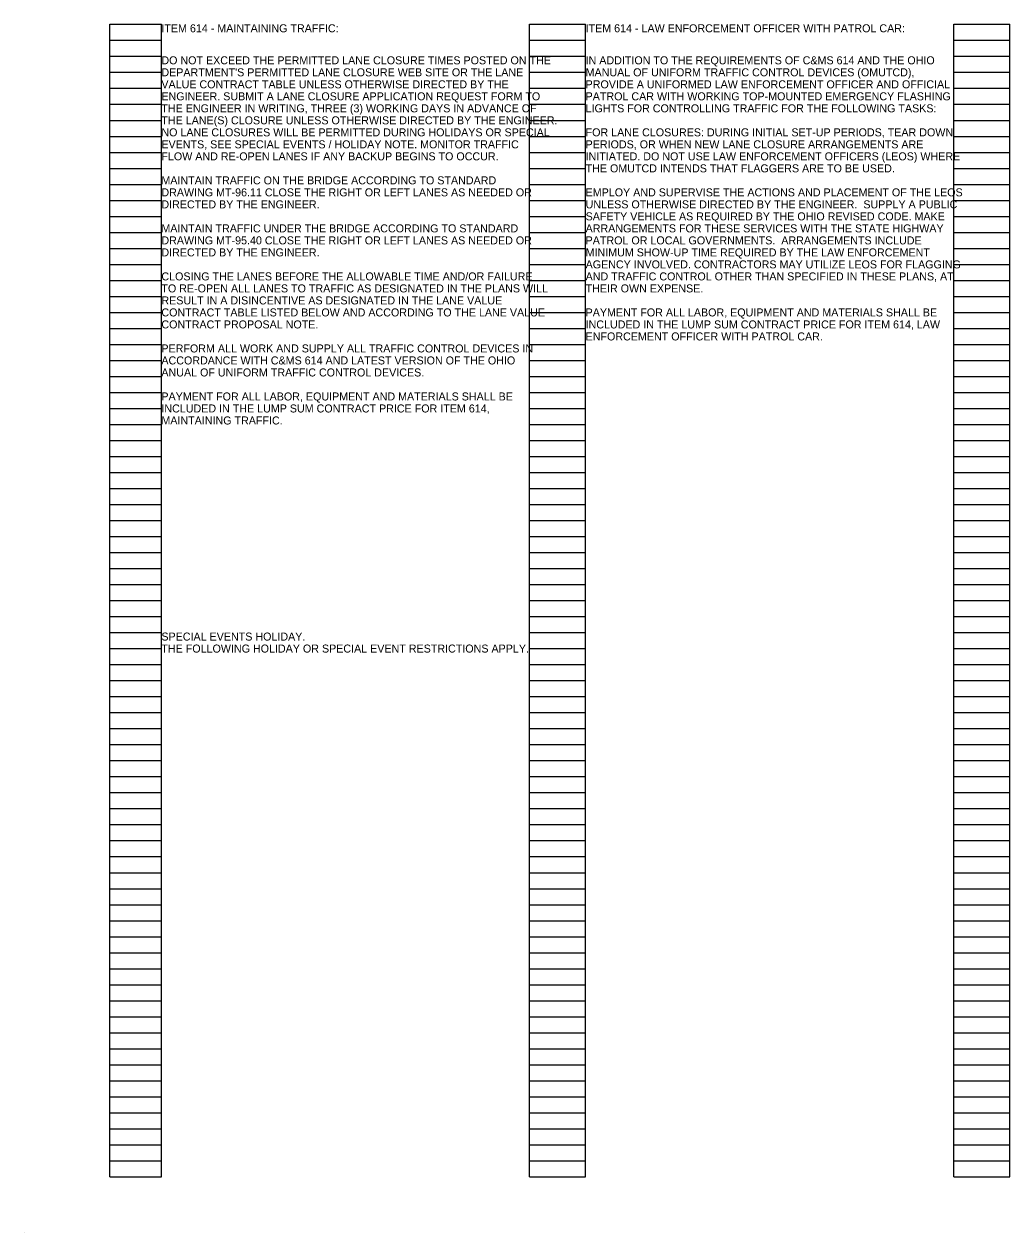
# Model space of a CAD drawing. Extents: x -36 to 68, y -39 to 86.
# Drawn here: x -36 to -18.76, y 0 to 21.14 of the extents above; entities that cross this region are included whole.
import ezdxf

# ---------------------------------------------------------------- set-up
doc = ezdxf.new("R2010")
doc.units = 0
doc.layers.add('SH_Data', color=7, linetype='Continuous')
doc.layers.add('ST_Text', color=7, linetype='Continuous')

msp = doc.modelspace()

# ---------------------------------------------------------------- linework, layer by layer
at = {"layer": 'SH_Data'}
for p, q in [((-34.5, 0.98), (-34.5, 21.14)), ((-34.5, 21.14), (-33.6, 21.14)), ((-33.6, 0.98), (-33.6, 21.14)), ((-27.16, 0.98), (-27.16, 21.14)), ((-27.16, 21.14), (-26.18, 21.14)), ((-26.18, 0.98), (-26.18, 21.14)), ((-19.74, 0.98), (-19.74, 21.14)), ((-19.74, 21.14), (-18.76, 21.14)), ((-18.76, 0.98), (-18.76, 21.14)), ((-34.5, 20.86), (-33.6, 20.86)), ((-27.16, 20.86), (-26.18, 20.86)), ((-19.74, 20.86), (-18.76, 20.86)), ((-34.5, 20.58), (-33.6, 20.58)), ((-27.16, 20.58), (-26.18, 20.58)), ((-19.74, 20.58), (-18.76, 20.58)), ((-34.5, 20.3), (-33.6, 20.3)), ((-27.16, 20.3), (-26.18, 20.3)), ((-19.74, 20.3), (-18.76, 20.3)), ((-34.5, 20.02), (-33.6, 20.02)), ((-27.16, 20.02), (-26.18, 20.02)), ((-19.74, 20.02), (-18.76, 20.02)), ((-34.5, 19.74), (-33.6, 19.74)), ((-27.16, 19.74), (-26.18, 19.74)), ((-19.74, 19.74), (-18.76, 19.74)), ((-34.5, 19.46), (-33.6, 19.46)), ((-27.16, 19.46), (-26.18, 19.46)), ((-19.74, 19.46), (-18.76, 19.46)), ((-34.5, 19.18), (-33.6, 19.18)), ((-27.16, 19.18), (-26.18, 19.18)), ((-19.74, 19.18), (-18.76, 19.18)), ((-34.5, 18.9), (-33.6, 18.9)), ((-27.16, 18.9), (-26.18, 18.9)), ((-19.74, 18.9), (-18.76, 18.9)), ((-34.5, 18.62), (-33.6, 18.62)), ((-27.16, 18.62), (-26.18, 18.62)), ((-19.74, 18.62), (-18.76, 18.62)), ((-34.5, 18.34), (-33.6, 18.34)), ((-27.16, 18.34), (-26.18, 18.34)), ((-19.74, 18.34), (-18.76, 18.34)), ((-34.5, 18.06), (-33.6, 18.06)), ((-27.16, 18.06), (-26.18, 18.06)), ((-19.74, 18.06), (-18.76, 18.06)), ((-34.5, 17.78), (-33.6, 17.78)), ((-27.16, 17.78), (-26.18, 17.78)), ((-19.74, 17.78), (-18.76, 17.78)), ((-34.5, 17.5), (-33.6, 17.5)), ((-27.16, 17.5), (-26.18, 17.5)), ((-19.74, 17.5), (-18.76, 17.5)), ((-34.5, 17.22), (-33.6, 17.22)), ((-27.16, 17.22), (-26.18, 17.22)), ((-19.74, 17.22), (-18.76, 17.22)), ((-34.5, 16.94), (-33.6, 16.94)), ((-27.16, 16.94), (-26.18, 16.94)), ((-19.74, 16.94), (-18.76, 16.94)), ((-34.5, 16.66), (-33.6, 16.66)), ((-27.16, 16.66), (-26.18, 16.66)), ((-19.74, 16.66), (-18.76, 16.66)), ((-34.5, 16.38), (-33.6, 16.38)), ((-27.16, 16.38), (-26.18, 16.38)), ((-19.74, 16.38), (-18.76, 16.38)), ((-34.5, 16.1), (-33.6, 16.1)), ((-27.16, 16.1), (-26.18, 16.1)), ((-19.74, 16.1), (-18.76, 16.1)), ((-34.5, 15.82), (-33.6, 15.82)), ((-27.16, 15.82), (-26.18, 15.82)), ((-19.74, 15.82), (-18.76, 15.82)), ((-34.5, 15.54), (-33.6, 15.54)), ((-27.16, 15.54), (-26.18, 15.54)), ((-19.74, 15.54), (-18.76, 15.54)), ((-34.5, 15.26), (-33.6, 15.26)), ((-27.16, 15.26), (-26.18, 15.26)), ((-19.74, 15.26), (-18.76, 15.26)), ((-34.5, 14.98), (-33.6, 14.98)), ((-27.16, 14.98), (-26.18, 14.98)), ((-19.74, 14.98), (-18.76, 14.98)), ((-34.5, 14.7), (-33.6, 14.7)), ((-27.16, 14.7), (-26.18, 14.7)), ((-19.74, 14.7), (-18.76, 14.7)), ((-34.5, 14.42), (-33.6, 14.42)), ((-27.16, 14.42), (-26.18, 14.42)), ((-19.74, 14.42), (-18.76, 14.42)), ((-34.5, 14.14), (-33.6, 14.14)), ((-27.16, 14.14), (-26.18, 14.14)), ((-19.74, 14.14), (-18.76, 14.14)), ((-34.5, 13.86), (-33.6, 13.86)), ((-27.16, 13.86), (-26.18, 13.86)), ((-19.74, 13.86), (-18.76, 13.86)), ((-34.5, 13.58), (-33.6, 13.58)), ((-27.16, 13.58), (-26.18, 13.58)), ((-19.74, 13.58), (-18.76, 13.58)), ((-34.5, 13.3), (-33.6, 13.3)), ((-27.16, 13.3), (-26.18, 13.3)), ((-19.74, 13.3), (-18.76, 13.3)), ((-34.5, 13.02), (-33.6, 13.02)), ((-27.16, 13.02), (-26.18, 13.02)), ((-19.74, 13.02), (-18.76, 13.02)), ((-34.5, 12.74), (-33.6, 12.74)), ((-27.16, 12.74), (-26.18, 12.74)), ((-19.74, 12.74), (-18.76, 12.74)), ((-34.5, 12.46), (-33.6, 12.46)), ((-27.16, 12.46), (-26.18, 12.46)), ((-19.74, 12.46), (-18.76, 12.46)), ((-34.5, 12.18), (-33.6, 12.18)), ((-27.16, 12.18), (-26.18, 12.18)), ((-19.74, 12.18), (-18.76, 12.18)), ((-34.5, 11.9), (-33.6, 11.9)), ((-27.16, 11.9), (-26.18, 11.9)), ((-19.74, 11.9), (-18.76, 11.9)), ((-34.5, 11.62), (-33.6, 11.62)), ((-27.16, 11.62), (-26.18, 11.62)), ((-19.74, 11.62), (-18.76, 11.62)), ((-34.5, 11.34), (-33.6, 11.34)), ((-27.16, 11.34), (-26.18, 11.34)), ((-19.74, 11.34), (-18.76, 11.34)), ((-34.5, 11.06), (-33.6, 11.06)), ((-27.16, 11.06), (-26.18, 11.06)), ((-19.74, 11.06), (-18.76, 11.06)), ((-34.5, 10.78), (-33.6, 10.78)), ((-27.16, 10.78), (-26.18, 10.78)), ((-19.74, 10.78), (-18.76, 10.78)), ((-34.5, 10.5), (-33.6, 10.5)), ((-27.16, 10.5), (-26.18, 10.5)), ((-19.74, 10.5), (-18.76, 10.5)), ((-34.5, 10.22), (-33.6, 10.22)), ((-27.16, 10.22), (-26.18, 10.22)), ((-19.74, 10.22), (-18.76, 10.22)), ((-34.5, 9.94), (-33.6, 9.94)), ((-27.16, 9.94), (-26.18, 9.94)), ((-19.74, 9.94), (-18.76, 9.94)), ((-34.5, 9.66), (-33.6, 9.66)), ((-27.16, 9.66), (-26.18, 9.66)), ((-19.74, 9.66), (-18.76, 9.66)), ((-34.5, 9.38), (-33.6, 9.38)), ((-27.16, 9.38), (-26.18, 9.38)), ((-19.74, 9.38), (-18.76, 9.38)), ((-34.5, 9.1), (-33.6, 9.1)), ((-27.16, 9.1), (-26.18, 9.1)), ((-19.74, 9.1), (-18.76, 9.1)), ((-34.5, 8.82), (-33.6, 8.82)), ((-27.16, 8.82), (-26.18, 8.82)), ((-19.74, 8.82), (-18.76, 8.82)), ((-34.5, 8.54), (-33.6, 8.54)), ((-27.16, 8.54), (-26.18, 8.54)), ((-19.74, 8.54), (-18.76, 8.54)), ((-34.5, 8.26), (-33.6, 8.26)), ((-27.16, 8.26), (-26.18, 8.26)), ((-19.74, 8.26), (-18.76, 8.26)), ((-34.5, 7.98), (-33.6, 7.98)), ((-27.16, 7.98), (-26.18, 7.98)), ((-19.74, 7.98), (-18.76, 7.98)), ((-34.5, 7.7), (-33.6, 7.7)), ((-27.16, 7.7), (-26.18, 7.7)), ((-19.74, 7.7), (-18.76, 7.7)), ((-34.5, 7.42), (-33.6, 7.42)), ((-27.16, 7.42), (-26.18, 7.42)), ((-19.74, 7.42), (-18.76, 7.42)), ((-34.5, 7.14), (-33.6, 7.14)), ((-27.16, 7.14), (-26.18, 7.14)), ((-19.74, 7.14), (-18.76, 7.14)), ((-34.5, 6.86), (-33.6, 6.86)), ((-27.16, 6.86), (-26.18, 6.86)), ((-19.74, 6.86), (-18.76, 6.86)), ((-34.5, 6.58), (-33.6, 6.58)), ((-27.16, 6.58), (-26.18, 6.58)), ((-19.74, 6.58), (-18.76, 6.58)), ((-34.5, 6.3), (-33.6, 6.3)), ((-27.16, 6.3), (-26.18, 6.3)), ((-19.74, 6.3), (-18.76, 6.3)), ((-34.5, 6.02), (-33.6, 6.02)), ((-27.16, 6.02), (-26.18, 6.02)), ((-19.74, 6.02), (-18.76, 6.02)), ((-34.5, 5.74), (-33.6, 5.74)), ((-27.16, 5.74), (-26.18, 5.74)), ((-19.74, 5.74), (-18.76, 5.74)), ((-34.5, 5.46), (-33.6, 5.46)), ((-27.16, 5.46), (-26.18, 5.46)), ((-19.74, 5.46), (-18.76, 5.46)), ((-34.5, 5.18), (-33.6, 5.18)), ((-27.16, 5.18), (-26.18, 5.18)), ((-19.74, 5.18), (-18.76, 5.18)), ((-34.5, 4.9), (-33.6, 4.9)), ((-27.16, 4.9), (-26.18, 4.9)), ((-19.74, 4.9), (-18.76, 4.9)), ((-34.5, 4.62), (-33.6, 4.62)), ((-27.16, 4.62), (-26.18, 4.62)), ((-19.74, 4.62), (-18.76, 4.62)), ((-34.5, 4.34), (-33.6, 4.34)), ((-27.16, 4.34), (-26.18, 4.34)), ((-19.74, 4.34), (-18.76, 4.34)), ((-34.5, 4.06), (-33.6, 4.06)), ((-27.16, 4.06), (-26.18, 4.06)), ((-19.74, 4.06), (-18.76, 4.06)), ((-34.5, 3.78), (-33.6, 3.78)), ((-27.16, 3.78), (-26.18, 3.78)), ((-19.74, 3.78), (-18.76, 3.78)), ((-34.5, 3.5), (-33.6, 3.5)), ((-27.16, 3.5), (-26.18, 3.5)), ((-19.74, 3.5), (-18.76, 3.5)), ((-34.5, 3.22), (-33.6, 3.22)), ((-27.16, 3.22), (-26.18, 3.22)), ((-19.74, 3.22), (-18.76, 3.22)), ((-34.5, 2.94), (-33.6, 2.94)), ((-27.16, 2.94), (-26.18, 2.94)), ((-19.74, 2.94), (-18.76, 2.94)), ((-34.5, 2.66), (-33.6, 2.66)), ((-27.16, 2.66), (-26.18, 2.66)), ((-19.74, 2.66), (-18.76, 2.66)), ((-34.5, 2.38), (-33.6, 2.38)), ((-27.16, 2.38), (-26.18, 2.38)), ((-19.74, 2.38), (-18.76, 2.38)), ((-34.5, 2.1), (-33.6, 2.1)), ((-27.16, 2.1), (-26.18, 2.1)), ((-19.74, 2.1), (-18.76, 2.1)), ((-34.5, 1.82), (-33.6, 1.82)), ((-27.16, 1.82), (-26.18, 1.82)), ((-19.74, 1.82), (-18.76, 1.82)), ((-34.5, 1.54), (-33.6, 1.54)), ((-27.16, 1.54), (-26.18, 1.54)), ((-19.74, 1.54), (-18.76, 1.54)), ((-34.5, 1.26), (-33.6, 1.26)), ((-27.16, 1.26), (-26.18, 1.26)), ((-19.74, 1.26), (-18.76, 1.26)), ((-34.5, 0.98), (-33.6, 0.98)), ((-27.16, 0.98), (-26.18, 0.98)), ((-19.74, 0.98), (-18.76, 0.98)), ((-36, 0), (-36, 0))]:
    msp.add_line(p, q, dxfattribs=at)

# ---------------------------------------------------------------- texts
at = {"layer": 'ST_Text'}
for s, p in [('ITEM 614 - MAINTAINING TRAFFIC:', (-33.6, 21)), ('ITEM 614 - LAW ENFORCEMENT OFFICER WITH PATROL CAR:', (-26.18, 21)), ('DO NOT EXCEED THE PERMITTED LANE CLOSURE TIMES POSTED ON THE ', (-33.6, 20.44)), ('IN ADDITION TO THE REQUIREMENTS OF C&MS 614 AND THE OHIO ', (-26.18, 20.44)), ("DEPARTMENT'S PERMITTED LANE CLOSURE WEB SITE OR THE LANE ", (-33.6, 20.23)), ('MANUAL OF UNIFORM TRAFFIC CONTROL DEVICES (OMUTCD), ', (-26.18, 20.23)), ('VALUE CONTRACT TABLE UNLESS OTHERWISE DIRECTED BY THE ', (-33.6, 20.02)), ('PROVIDE A UNIFORMED LAW ENFORCEMENT OFFICER AND OFFICIAL ', (-26.18, 20.02)), ('ENGINEER. SUBMIT A LANE CLOSURE APPLICATION REQUEST FORM TO ', (-33.6, 19.81)), ('PATROL CAR WITH WORKING TOP-MOUNTED EMERGENCY FLASHING ', (-26.18, 19.81)), ('THE ENGINEER IN WRITING, THREE (3) WORKING DAYS IN ADVANCE OF ', (-33.6, 19.6)), ('LIGHTS FOR CONTROLLING TRAFFIC FOR THE FOLLOWING TASKS:', (-26.18, 19.6)), ('THE LANE(S) CLOSURE UNLESS OTHERWISE DIRECTED BY THE ENGINEER. ', (-33.6, 19.39)), ('NO LANE CLOSURES WILL BE PERMITTED DURING HOLIDAYS OR SPECIAL ', (-33.6, 19.18)), ('FOR LANE CLOSURES: DURING INITIAL SET-UP PERIODS, TEAR DOWN ', (-26.18, 19.18)), ('EVENTS, SEE SPECIAL EVENTS / HOLIDAY NOTE. MONITOR TRAFFIC ', (-33.6, 18.97)), ('PERIODS, OR WHEN NEW LANE CLOSURE ARRANGEMENTS ARE ', (-26.18, 18.97)), ('FLOW AND RE-OPEN LANES IF ANY BACKUP BEGINS TO OCCUR.', (-33.6, 18.76)), ('INITIATED. DO NOT USE LAW ENFORCEMENT OFFICERS (LEOS) WHERE ', (-26.18, 18.76)), ('THE OMUTCD INTENDS THAT FLAGGERS ARE TO BE USED.', (-26.18, 18.55)), ('MAINTAIN TRAFFIC ON THE BRIDGE ACCORDING TO STANDARD ', (-33.6, 18.34)), ('DRAWING MT-96.11 CLOSE THE RIGHT OR LEFT LANES AS NEEDED OR ', (-33.6, 18.13)), ('EMPLOY AND SUPERVISE THE ACTIONS AND PLACEMENT OF THE LEOS ', (-26.18, 18.13)), ('DIRECTED BY THE ENGINEER. ', (-33.6, 17.92)), ('UNLESS OTHERWISE DIRECTED BY THE ENGINEER.  SUPPLY A PUBLIC ', (-26.18, 17.92)), ('SAFETY VEHICLE AS REQUIRED BY THE OHIO REVISED CODE. MAKE ', (-26.18, 17.71)), ('MAINTAIN TRAFFIC UNDER THE BRIDGE ACCORDING TO STANDARD ', (-33.6, 17.5)), ('ARRANGEMENTS FOR THESE SERVICES WITH THE STATE HIGHWAY ', (-26.18, 17.5)), ('DRAWING MT-95.40 CLOSE THE RIGHT OR LEFT LANES AS NEEDED OR ', (-33.6, 17.29)), ('PATROL OR LOCAL GOVERNMENTS.  ARRANGEMENTS INCLUDE ', (-26.18, 17.29)), ('DIRECTED BY THE ENGINEER.', (-33.6, 17.08)), ('MINIMUM SHOW-UP TIME REQUIRED BY THE LAW ENFORCEMENT ', (-26.18, 17.08)), ('AGENCY INVOLVED. CONTRACTORS MAY UTILIZE LEOS FOR FLAGGING ', (-26.18, 16.87)), ('CLOSING THE LANES BEFORE THE ALLOWABLE TIME AND/OR FAILURE ', (-33.6, 16.66)), ('AND TRAFFIC CONTROL OTHER THAN SPECIFIED IN THESE PLANS, AT ', (-26.18, 16.66)), ('TO RE-OPEN ALL LANES TO TRAFFIC AS DESIGNATED IN THE PLANS WILL ', (-33.6, 16.45)), ('THEIR OWN EXPENSE.  ', (-26.18, 16.45)), ('RESULT IN A DISINCENTIVE AS DESIGNATED IN THE LANE VALUE ', (-33.6, 16.24)), ('CONTRACT TABLE LISTED BELOW AND ACCORDING TO THE LANE VALUE ', (-33.6, 16.03)), ('PAYMENT FOR ALL LABOR, EQUIPMENT AND MATERIALS SHALL BE ', (-26.18, 16.03)), ('CONTRACT PROPOSAL NOTE.', (-33.6, 15.82)), ('INCLUDED IN THE LUMP SUM CONTRACT PRICE FOR ITEM 614, LAW ', (-26.18, 15.82)), ('ENFORCEMENT OFFICER WITH PATROL CAR.  ', (-26.18, 15.61)), ('PERFORM ALL WORK AND SUPPLY ALL TRAFFIC CONTROL DEVICES IN ', (-33.6, 15.4)), ('ACCORDANCE WITH C&MS 614 AND LATEST VERSION OF THE OHIO ', (-33.6, 15.19)), ('ANUAL OF UNIFORM TRAFFIC CONTROL DEVICES.', (-33.6, 14.98)), ('PAYMENT FOR ALL LABOR, EQUIPMENT AND MATERIALS SHALL BE ', (-33.6, 14.56)), ('INCLUDED IN THE LUMP SUM CONTRACT PRICE FOR ITEM 614, ', (-33.6, 14.35)), ('MAINTAINING TRAFFIC.', (-33.6, 14.14)), ('SPECIAL EVENTS HOLIDAY.', (-33.6, 10.36)), ('THE FOLLOWING HOLIDAY OR SPECIAL EVENT RESTRICTIONS APPLY.', (-33.6, 10.15))]:
    msp.add_text(s, height=0.14, dxfattribs=at).set_placement(p)

doc.saveas('drawing.dxf')
